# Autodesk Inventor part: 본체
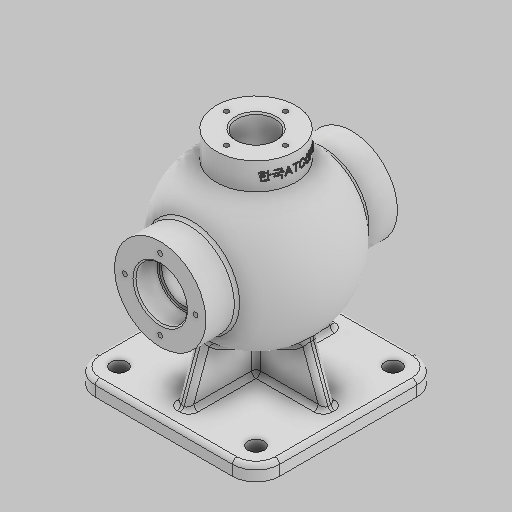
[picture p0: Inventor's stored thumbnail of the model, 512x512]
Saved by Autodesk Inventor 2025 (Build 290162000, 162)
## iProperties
Created: 2024-07
Part Number: 본체
Material: 일반
Document SubType Name: Modeling
Designer: 현기
Density: 1 g/cm^3
Appearance: 기본값
Author: 현기
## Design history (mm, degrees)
sketch "스케치1"
  geometry: L1 (-62.5, 62.5)-(62.5, 62.5); L2 (62.5, 62.5)-(62.5, -62.5); L3 (62.5, -62.5)-(-62.5, -62.5); L4 (-62.5, -62.5)-(-62.5, 62.5); L5 (-62.5, 62.5)-(62.5, -62.5); L6 (62.5, 62.5)-(-62.5, -62.5); 1 further point
  constraints: 12 end point, 2 midpoint, 2 parallel, 1 horizontal, 1 perpendicular
  dimensions: "d0" = 125 distance of L2.end L3.end; "d1" = 125 distance of L1.end L2.end
extrude "돌출1" new body sketch "스케치1" distance "d2" = 10; taper "d3" = 0 deg
sketch "스케치2"
  geometry: L1 (0, 0)-(0, 85); L2 (0, 149.344)-(0, 26.445); A1 r 44 centre (0, 85) between (0, 41) and (0, 129); A2 r 54 centre (0, 85) between (0, 31) and (0, 139)
  constraints: 5 point on line, 4 end point, 4 point on circle, 2 centre point, 2 coincident, 1 vertical
  dimensions: "d4" = 85 distance of L1.start L1.end; "d6" = 44 radius of A1; "d7" = 54 radius of A2
revolve "회전1" sketch "스케치2" stored, may be unused: angle "d8" = 90 deg
node "작업 평면1"
sketch "스케치3"
  geometry: C1 r 31 at (0, 85); 1 further point
  constraints: 1 centre point
  dimensions: "d10" = 62 diameter of C1
extrude "돌출2" join sketch "스케치3" stored distance "d11" = 130; taper "d12" = 0 deg
node "작업 평면2"
sketch "스케치4"
  geometry: C1 r 27 at (0, 0); 1 further point
  constraints: 1 centre point, 1 coincident
  dimensions: "d14" = 54 diameter of C1
extrude "돌출3" join sketch "스케치4" stored distance "d15" = 10; taper "d16" = 0 deg
sketch "스케치5"
  geometry: L1 (-62.5, 10)-(62.5, 10) reference; L2 (-62.5, 10)-(-50.5, 10); L3 (-50.5, 10)-(-36.565, 48.286); L4 (-62.5, 0)-(-62.5, 10) reference; L5 (-50.5, 10)-(0, 10); L6 (0, 10)-(0, 34.977); L7 (0, 34.977)-(-36.565, 48.286); 1 further point
  constraints: 10 end point, 2 point on line, 1 midpoint, 1 vertical
  dimensions: "d17" = 12 distance of L1.start L2.end; "d18" = 20 deg angle of L3 L4
extrude "돌출4" join sketch "스케치5" stored distance "d19" = 8; taper "d20" = 0 deg
fillet "모깎기1" dims "d28" = 16
fillet "모깎기2" dims "d29" = 3
fillet "모깎기3" dims "d30" = 3
fillet "모깎기4" dims "d31" = 3
fillet "모깎기5" dims "d32" = 3
sketch "스케치6"
  geometry: C1 r 31 at (0, 0) reference; 2 further points
  constraints: 1 coincident
hole "구멍1" sketch "스케치6" at (0, 0) diameter "d33" = 30; stored, may be unused: countersink angle "d37" = 90 deg, drill point angle "d39" = 0 deg; dims "d34" = 11, "d35" = 35, "d36" = 16, "d38" = 50
sketch "스케치7"
  geometry: C1 r 31 at (0, 0) reference; 2 further points
  constraints: 1 coincident
hole "구멍2" sketch "스케치7" at (0, 0) diameter "d40" = 30; stored, may be unused: countersink angle "d44" = 90 deg, drill point angle "d46" = 0 deg; dims "d41" = 6, "d42" = 35, "d43" = 16, "d45" = 50
fillet "모깎기6" dims "d47" = 0.6
sketch "스케치8"
  geometry: C1 r 27 at (0, 0) reference; 2 further points
  constraints: 1 coincident
hole "구멍3" sketch "스케치8" at (0, 0) diameter "d48" = 26; stored, may be unused: countersink angle "d52" = 90 deg, drill point angle "d54" = 0 deg; dims "d49" = 6, "d50" = 35, "d51" = 16, "d53" = 50
chamfer "모따기1" distance "d55" = 1; stored, may be unused: second distance "d56" = 2, angle "d57" = 45 deg
sketch "스케치9" dims "d58" = 48
  geometry: L1 (0, 49.505)-(0, -35.875); L2 (-27, 46.765)-(27, 46.765) reference; 3 further points
  constraints: 2 end point, 1 perpendicular, 1 point on line, 1 vertical alignment, 2 other
hole "구멍4" sketch "스케치9" at (0, 24) diameter "d59" = 3.242; stored, may be unused: countersink angle "d63" = 90 deg, drill point angle "d65" = 120 deg; dims "d60" = 12, "d61" = 4, "d62" = 2, "d64" = 15
sketch "스케치10" dims "d69" = 40
  geometry: L1 (0, 33.22)-(0, -33.562); C1 r 13 at (0, 0) reference; 3 further points
  constraints: 2 end point, 1 coincident, 1 point on line, 1 vertical, 1 vertical alignment, 2 other
hole "구멍5" sketch "스케치10" at (0, 20) diameter "d70" = 3.242; stored, may be unused: countersink angle "d74" = 90 deg, drill point angle "d76" = 120 deg; dims "d71" = 9, "d72" = 4, "d73" = 2, "d75" = 11
sketch "스케치11"
  geometry: A1 r 16 centre (-46.5, 46.5) between (-46.5, 62.5) and (-62.5, 46.5) reference; A2 r 16 centre (46.5, 46.5) between (62.5, 46.5) and (46.5, 62.5) reference; A3 r 16 centre (46.5, -46.5) between (46.5, -62.5) and (62.5, -46.5) reference; A4 r 16 centre (-46.5, -46.5) between (-62.5, -46.5) and (-46.5, -62.5) reference; 5 further points
  constraints: 4 coincident
hole "구멍6" sketch "스케치11" at (-46.5, 46.5), (46.5, 46.5), (46.5, -46.5), (-46.5, -46.5) diameter "d80" = 11; stored, may be unused: countersink angle "d84" = 90 deg, drill point angle "d86" = 120 deg; dims "d81" = 9, "d82" = 4, "d83" = 2, "d85" = 11
node "작업 평면3"
sketch "스케치12"
  geometry: L1 (0, 46.5)-(0, -46.5) reference; L2 (150, -27)-(150, 27) reference; 3 further points
  constraints: 1 horizontal alignment, 1 midpoint, 1 other
  dimensions: "d88" = 9 distance from line of L2 point (141, 0)
feature "엠보싱1" sketch "스케치12" dims "d0" = 125, "d1" = 125, "d89" = 0.5, "d90" = 0
sketch "스케치13"
  geometry: L1 (109, 0)-(109, 7) reference; L2 (109, 7)-(97, 7); L3 (109, 7)-(93, 7) reference; L4 (97, 7)-(97, 10.686); 1 further point
  constraints: 4 end point, 1 perpendicular, 1 point on line
  dimensions: "d91" = 12 distance of L1.end L2.end
feature "Ư耀Ʊ耀Ƴ耀Ƶ耀Ʒ耀ƹ耀ƻ耀ƽ耀" dims "d0" = 125, "d1" = 125, "d2" = 10, "d3" = 0, "d4" = 85, "d6" = 44, "d7" = 54, "d8" = 90 deg, "d9" = 65, "d10" = 62, "d11" = 130, "d12" = 0, "d13" = 150, "d14" = 54, "d15" = 10, "d16" = 0, "d17" = 12, "d18" = 20 deg, "d19" = 8, "d20" = 0, "d21" = 0.5, "d22" = 2, "d23" = 0, "d24" = 20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
node "솔리드1"
mirror "미러1"
pattern_circular "원형 패턴1" dims angle "d26" = 360 deg
pattern_circular "원형 패턴2" dims angle "d67" = 360 deg
mirror "미러2"
pattern_circular "원형 패턴3" dims angle "d78" = 360 deg
feature "A9D066F2-1C7D-4E18-AEED-F7BC21143FA4" dims "d33" = 30, "d34" = 11, "d35" = 35, "d36" = 16, "d37" = 90 deg, "d38" = 50, "d39" = 0
